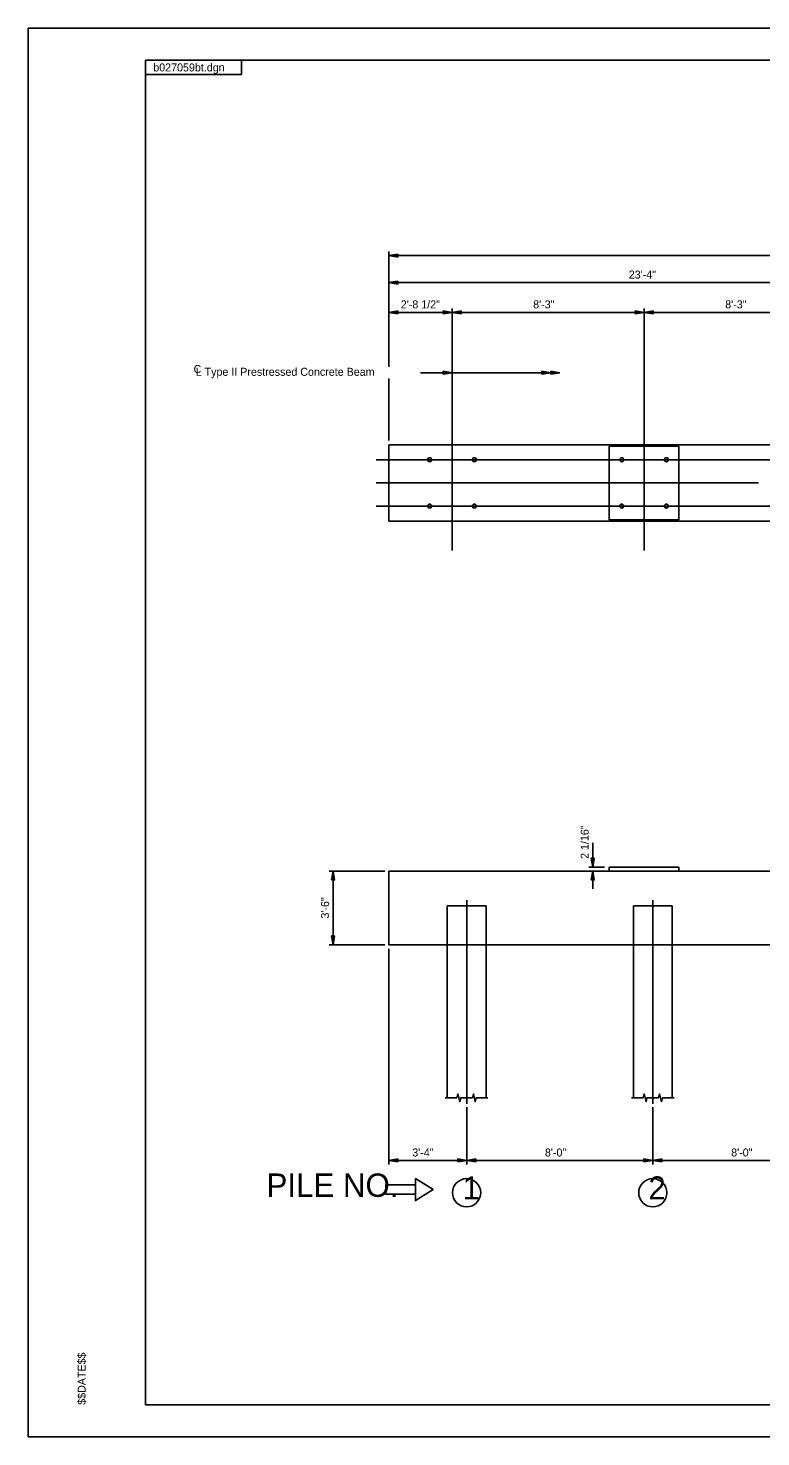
# Model space of a CAD drawing. Extents: x 437 to 537, y 571 to 720.
# Drawn here: x 437.2 to 468.7, y 570.8 to 631.3 of the extents above; entities that cross this region are included whole.
import ezdxf

# ---------------------------------------------------------------- set-up
doc = ezdxf.new("R2010")
doc.units = 0
for name, color, linetype in [('BR_AUTO DIMENSION', 7, 'Continuous'), ('BR_BORDER LINES', 7, 'Continuous'), ('BR_CENTER LINES', 7, 'Continuous'), ('BR_CONCRETE', 7, 'Continuous'), ('BR_PRESTRESSED BEAM', 7, 'Continuous'), ('BR_STRUCTURAL STEEL', 7, 'Continuous'), ('BR_TABLE LINES', 7, 'Continuous'), ('BR_TEXT', 7, 'Continuous'), ('RD_SHT_IplotShp', 7, 'Continuous')]:
    doc.layers.add(name, color=color, linetype=linetype)

msp = doc.modelspace()

# ---------------------------------------------------------------- linework, layer by layer
at = {"layer": 'BR_AUTO DIMENSION'}
for p, q in [((452.689, 616.723), (452.689, 621.674)), ((452.689, 621.503), (453.075, 621.567)), ((452.689, 621.503), (499.355, 621.503)), ((453.076, 621.438), (452.689, 621.503)), ((453.075, 621.567), (453.076, 621.438)), ((452.689, 620.34), (453.075, 620.404)), ((476.022, 620.34), (452.689, 620.34)), ((453.076, 620.275), (452.689, 620.34)), ((453.075, 620.404), (453.076, 620.275)), ((452.689, 619.06), (453.075, 619.124)), ((452.689, 619.06), (455.397, 619.06)), ((453.076, 618.995), (452.689, 619.06)), ((453.075, 619.124), (453.076, 618.995)), ((455.397, 619.06), (455.01, 619.124)), ((455.01, 619.124), (455.01, 618.995)), ((455.01, 618.995), (455.397, 619.06)), ((455.397, 618.873), (455.397, 619.232)), ((455.397, 619.06), (455.784, 619.124)), ((455.397, 619.06), (463.647, 619.06)), ((455.784, 618.995), (455.397, 619.06)), ((455.784, 619.124), (455.784, 618.995)), ((463.647, 619.06), (463.26, 619.124)), ((463.26, 619.124), (463.26, 618.995)), ((463.26, 618.995), (463.647, 619.06)), ((463.647, 618.873), (463.647, 619.232)), ((463.647, 619.06), (464.034, 619.124)), ((463.647, 619.06), (471.897, 619.06)), ((464.034, 618.995), (463.647, 619.06)), ((464.034, 619.124), (464.034, 618.995)), ((455.397, 616.468), (455.01, 616.533)), ((455.01, 616.533), (455.01, 616.404)), ((459.645, 616.468), (459.258, 616.533)), ((459.258, 616.533), (459.258, 616.404)), ((460.031, 616.468), (459.645, 616.533)), ((459.645, 616.533), (459.645, 616.404)), ((452.689, 614.127), (452.689, 616.219)), ((454.04, 616.468), (460.031, 616.468)), ((455.01, 616.404), (455.397, 616.468)), ((458.344, 616.468), (455.397, 616.468)), ((459.258, 616.404), (459.645, 616.468)), ((459.645, 616.404), (460.031, 616.468)), ((452.689, 613.551), (452.689, 614.127)), ((461.445, 595.235), (461.445, 596.281)), ((461.445, 595.235), (461.38, 595.622)), ((461.38, 595.622), (461.509, 595.622)), ((461.509, 595.622), (461.445, 595.235)), ((452.517, 595.068), (450.116, 595.068)), ((450.288, 595.068), (450.223, 594.682)), ((450.288, 591.902), (450.288, 595.068)), ((450.352, 594.681), (450.288, 595.068)), ((461.942, 595.235), (461.273, 595.235)), ((461.445, 595.068), (461.38, 594.682)), ((461.445, 595.068), (461.445, 594.298)), ((461.509, 594.681), (461.445, 595.068)), ((450.223, 594.682), (450.352, 594.681)), ((461.38, 594.682), (461.509, 594.681)), ((452.517, 591.902), (450.116, 591.902)), ((450.288, 591.902), (450.223, 592.288)), ((450.223, 592.288), (450.352, 592.288)), ((450.352, 592.288), (450.288, 591.902)), ((452.689, 591.73), (452.689, 582.464)), ((456.027, 584.921), (456.027, 582.464)), ((464.027, 584.921), (464.027, 582.464)), ((452.689, 582.636), (453.075, 582.7)), ((456.022, 582.636), (452.689, 582.636)), ((453.076, 582.571), (452.689, 582.636)), ((453.075, 582.7), (453.076, 582.571)), ((456.027, 582.636), (455.64, 582.7)), ((455.64, 582.7), (455.64, 582.571)), ((455.64, 582.571), (456.027, 582.636)), ((456.022, 582.636), (464.022, 582.636)), ((456.027, 583.152), (456.027, 582.464)), ((456.027, 582.636), (456.413, 582.7)), ((456.413, 582.571), (456.027, 582.636)), ((456.413, 582.7), (456.413, 582.571)), ((464.027, 582.636), (463.64, 582.7)), ((463.64, 582.7), (463.64, 582.571)), ((463.64, 582.571), (464.027, 582.636)), ((464.022, 582.636), (474.355, 582.636)), ((464.027, 582.636), (464.413, 582.7)), ((464.413, 582.571), (464.027, 582.636)), ((464.413, 582.7), (464.413, 582.571))]:
    msp.add_line(p, q, dxfattribs=at)
for centre in [(456.022, 581.251), (464.022, 581.251)]:
    msp.add_circle(centre, 0.606, dxfattribs=at)
at = {"layer": 'BR_BORDER LINES'}
for p, q in [((442.23, 572.144), (442.231, 629.895)), ((534.816, 629.892), (442.231, 629.895)), ((442.231, 572.141), (442.231, 629.892)), ((534.814, 629.892), (442.231, 629.892)), ((446.356, 629.892), (446.356, 629.271)), ((442.231, 629.271), (446.356, 629.271)), ((442.23, 572.144), (534.814, 572.141)), ((442.231, 572.141), (534.814, 572.141))]:
    msp.add_line(p, q, dxfattribs=at)
at = {"layer": 'BR_CENTER LINES'}
for p, q in [((455.397, 608.838), (455.397, 618.873)), ((463.647, 616.724), (463.647, 618.873)), ((463.647, 608.838), (463.647, 616.724)), ((452.141, 612.732), (500.136, 612.732)), ((452.141, 611.736), (468.56, 611.736)), ((452.141, 610.74), (500.136, 610.74)), ((456.027, 593.818), (456.027, 591.902)), ((464.027, 593.818), (464.027, 591.902)), ((456.027, 591.902), (456.027, 585.068)), ((464.027, 591.902), (464.027, 585.068))]:
    msp.add_line(p, q, dxfattribs=at)
at = {"layer": 'BR_CONCRETE'}
for p, q in [((452.689, 613.378), (499.355, 613.378)), ((452.689, 610.094), (452.689, 613.378)), ((465.147, 613.315), (462.147, 613.315)), ((462.147, 610.157), (462.147, 613.315)), ((465.147, 610.157), (465.147, 613.315)), ((499.355, 610.094), (452.689, 610.094)), ((465.147, 610.157), (462.147, 610.157)), ((452.689, 591.902), (452.689, 595.068)), ((465.147, 595.068), (452.689, 595.068)), ((462.147, 595.068), (462.147, 595.235)), ((462.147, 595.235), (465.147, 595.235)), ((465.147, 595.235), (465.147, 595.068)), ((473.397, 595.068), (465.147, 595.068)), ((462.863, 591.902), (452.689, 591.902)), ((474.341, 591.902), (462.863, 591.902))]:
    msp.add_line(p, q, dxfattribs=at)
at = {"layer": 'BR_PRESTRESSED BEAM'}
for p, q in [((455.193, 591.902), (455.193, 593.568)), ((455.193, 593.568), (456.86, 593.568)), ((456.86, 593.568), (456.86, 591.902)), ((463.193, 591.902), (463.193, 593.568)), ((463.193, 593.568), (464.86, 593.568)), ((464.86, 593.568), (464.86, 591.902)), ((455.193, 591.902), (455.193, 585.326)), ((456.86, 591.902), (456.86, 585.326)), ((463.193, 591.902), (463.193, 585.326)), ((464.86, 591.902), (464.86, 585.326))]:
    msp.add_line(p, q, dxfattribs=at)
at = {"layer": 'BR_STRUCTURAL STEEL'}
for centre in [(454.439, 612.732), (456.355, 612.732), (462.689, 612.732), (464.605, 612.732), (454.439, 610.74), (456.355, 610.74), (462.689, 610.74), (464.605, 610.74)]:
    msp.add_circle(centre, 0.0859, dxfattribs=at)
at = {"layer": 'BR_TABLE LINES'}
for points in [[(455.105, 585.326), (455.605, 585.326), (455.647, 585.493), (455.73, 585.16), (455.772, 585.326), (456.022, 585.326)], [(456.022, 585.326), (456.272, 585.326), (456.314, 585.493), (456.397, 585.16), (456.439, 585.326), (456.939, 585.326)], [(463.105, 585.326), (463.605, 585.326), (463.647, 585.493), (463.73, 585.16), (463.772, 585.326), (464.022, 585.326)], [(464.022, 585.326), (464.272, 585.326), (464.314, 585.493), (464.397, 585.16), (464.439, 585.326), (464.939, 585.326)]]:
    msp.add_lwpolyline(points, dxfattribs=at)
at = {"layer": 'BR_TEXT'}
for points in [[(452.56, 581.588), (453.822, 581.588), (453.822, 581.186), (452.56, 581.186)], [(453.822, 581.861), (454.582, 581.387), (453.822, 580.913)]]:
    msp.add_lwpolyline(points, close=True, dxfattribs=at)
at = {"layer": 'RD_SHT_IplotShp'}
msp.add_lwpolyline([(437.19, 631.267), (536.19, 631.267), (536.19, 570.767), (437.19, 570.767)], close=True, dxfattribs=at)

# ---------------------------------------------------------------- texts
at = {"layer": 'BR_TEXT'}
for s, height, p in [('b027059bt.dgn', 0.34375, (442.563, 629.409)), ('L Type II Prestressed Concrete Beam', 0.34352, (444.385, 616.336)), ('8\'-0"', 0.3437, (459.388, 582.807)), ('8\'-0"', 0.3437, (467.388, 582.807)), ('1', 0.989, (455.855, 580.963)), ('2', 0.989, (463.839, 580.963))]:
    msp.add_text(s, height=height, dxfattribs=at).set_placement(p)
for s, height, rotation, p in [('23\'-4"', 0.3437, 360, (462.99, 620.512)), ('2\'-8 1/2"', 0.3438, 360, (453.197, 619.232)), ('8\'-3"', 0.3438, 360, (458.882, 619.232)), ('8\'-3"', 0.3438, 360, (467.132, 619.232)), ('C', 0.344, 360, (444.294, 616.456)), ('2 1/16"', 0.3437, 90, (461.268, 595.587)), ('3\'-6"', 0.3438, 90, (450.116, 593.024)), ('3\'-4"', 0.3438, 360, (453.689, 582.807)), ('PILE NO.', 1.0039, 360, (447.428, 581.073)), ('$$DATE$$', 0.3437, 89.99821, (439.659, 572.141))]:
    msp.add_text(s, height=height, rotation=rotation, dxfattribs=at).set_placement(p)

doc.saveas('drawing.dxf')
